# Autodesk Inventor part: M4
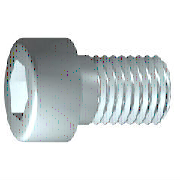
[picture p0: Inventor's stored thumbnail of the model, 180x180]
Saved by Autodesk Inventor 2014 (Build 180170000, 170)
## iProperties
IsCustomPart: 0
Company: 한국ATC센터
Created: 2014-10
Part Number: M4
Material: Steel, Mild
Description: 6각머리 태핑 나사
Document SubType Name: Modeling
Standard: KS B 1003
Designer: KYOUNG IL JANG
Standards Organization: KS
Language: ko-KR
Size Designation: M 4 x 10
Categories: <MemberInstance><Categories><Category DisplayName="조임쇠" InternalName="e4da775c-781d-43d5-af7c-5136215cf5a6" Mnemonic="FSTN"><Category DisplayName="볼트" InternalN
Density: 7.86 g/cm^3
Mass: 2.0371 g
Surface Area: 3.0572 cm^2
Volume: 0.259174 cm^3
Appearance: 검은색 캐스트
Author: KYOUNG IL JANG
Revision Number: 1
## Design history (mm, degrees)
sketch "스케치1"
  geometry: L1 (-1, 0)-(10, 0); L2 (10, 0)-(10, 2); L3 (10, 2)-(1.75, 2); L4 (1.75, 2)-(1.32, 2); L5 (1.32, 2)-(0, 2); L6 (0, 2)-(0, 3.5); L7 (0, 3.5)-(-4, 3.5); L8 (-4, 3.5)-(-4, 1.732); L9 (-4, 1.732)-(-2, 1.732); L10 (-2, 1.732)-(-1, 0); L11 (-6.8, 0)-(12.8, 0) reference; L12 (0, -0.7)-(0, 4.2) reference; L13 (1.75, 2)-(0, 2)
  constraints: 22 end point, 6 parallel, 2 collinear, 2 perpendicular, 1 horizontal, 1 point on line
  dimensions: "d1" = 8.25 distance from line of L3.end L2 (= GEL); "d2" = 0.42952 distance of L4.end L3.end (computed from GAL); "d3" = 4 distance between parallel lines of L8 L6 (= KOH); "d4" = 2 distance of L8.end L9.end (= INTI); "d5" = 60 deg angle of L10 L1; "d6" = 4 diameter of L3 L1 (= GD); "d7" = 4 diameter of L5 L1 (= BDM); "d8" = 3.4641 diameter of L9 L1 (= 1.1547 x SW); "d9" = 7 diameter of L7 L1 (= KOD); "d26" = 10 distance between parallel lines of L12 L2 (= NLG)
revolve "본체" sketch "스케치1" stored, may be unused: angle "d10" = 90 deg
sketch "스케치2"
  geometry: L1 (0, -4.9)-(0, 4.9) reference; L2 (-4.9, 0)-(4.9, 0) reference; L3 (1.732, 0)-(0.866, -1.5); L4 (0.866, -1.5)-(-0.866, -1.5); L5 (-0.866, -1.5)-(-1.732, 0); L6 (-1.732, 0)-(-0.866, 1.5); L7 (-0.866, 1.5)-(0.866, 1.5); L8 (0.866, 1.5)-(1.732, 0); 2 further points
  constraints: 12 end point, 1 coincident, 1 horizontal alignment, 1 point on line, 12 other
extrude "슬롯" join sketch "스케치2" stored distance "d11" = 10; taper "d12" = 0 deg
workplane "Work Plane1"
fillet "Fillet2" dims "d30" = 0.1 (= R)
body "Solid1"
fillet "모깎기1" dims "d17" = 0.4 (= RR)
feature "스레드" dims "d13" = 8.25 (= GEL), "d14" = 0
chamfer "모따기1" distance "d15" = 0.42941 (= -0.5 x SPD + 0.5 x GD); stored, may be unused: second distance "d16" = 0.42941 (= GUL), angle "d27" = 45 deg
other parameters: "GD" = 4 (= NND) [user parameter; used in 2 equation terms], "NLG" = 10 [user parameter; used in 1 equation term], "GEL" = 8.25 [user parameter; used in 2 equation terms], "KOD" = 7 [user parameter; used in 1 equation term], "KOH" = 4 [user parameter; used in 1 equation term], "INTI" = 2 [user parameter; used in 1 equation term], "GAL" = 0.42941 (= 0.61345 x PTC) [user parameter; used in 1 equation term], "GUL" = 0.42941 (= 0.61345 x PTC) [user parameter; used in 1 equation term], "BDM" = 4 (= NND) [user parameter; used in 1 equation term], "SW" = 3 [user parameter; used in 2 equation terms], "RR" = 0.4 [user parameter; used in 1 equation term], "SPD" = 3.14117 (= NND - 1.2269 x PTC) [user parameter; used in 1 equation term], "d19" = 0, "d28" = 0, "d29" = 0, "R" = 0.1 [user parameter; used in 1 equation term], "PHH" = 0.2 [user parameter], "GD1" = 3.14117 (= THREADDIA - 1.2269 x PTC) [user parameter], "THREADDIA" = 4 [user parameter; used in 1 equation term], "FAWI" = 45 deg [user parameter], "TPU" = 14.28571 (computed from PTC) [user parameter], "PTC" = 0.7 [user parameter; used in 5 equation terms], "NND" = 4 [user parameter; used in 3 equation terms], "TOA" = 30 deg [user parameter], "E0" = 3.465 (= 1.155 x SW) [user parameter]
